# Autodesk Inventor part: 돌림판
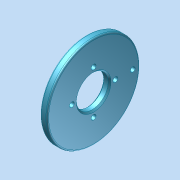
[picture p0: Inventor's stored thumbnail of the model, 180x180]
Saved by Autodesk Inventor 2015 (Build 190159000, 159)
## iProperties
Created: 2026-09
Part Number: 돌림판
Material: 일반
Document SubType Name: Modeling
Designer: SCD-A06
Density: 1 g/cm^3
Appearance: 기본값
Author: SCD-A06
Author: jhkim
Creation Date: 2026-08-27
Sending System: Autodesk Inventor 2027
Preprocessor: ST-DEVELOPER v20.1
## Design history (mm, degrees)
node "돌림판1"
node "솔리드1"
node "기준1"
